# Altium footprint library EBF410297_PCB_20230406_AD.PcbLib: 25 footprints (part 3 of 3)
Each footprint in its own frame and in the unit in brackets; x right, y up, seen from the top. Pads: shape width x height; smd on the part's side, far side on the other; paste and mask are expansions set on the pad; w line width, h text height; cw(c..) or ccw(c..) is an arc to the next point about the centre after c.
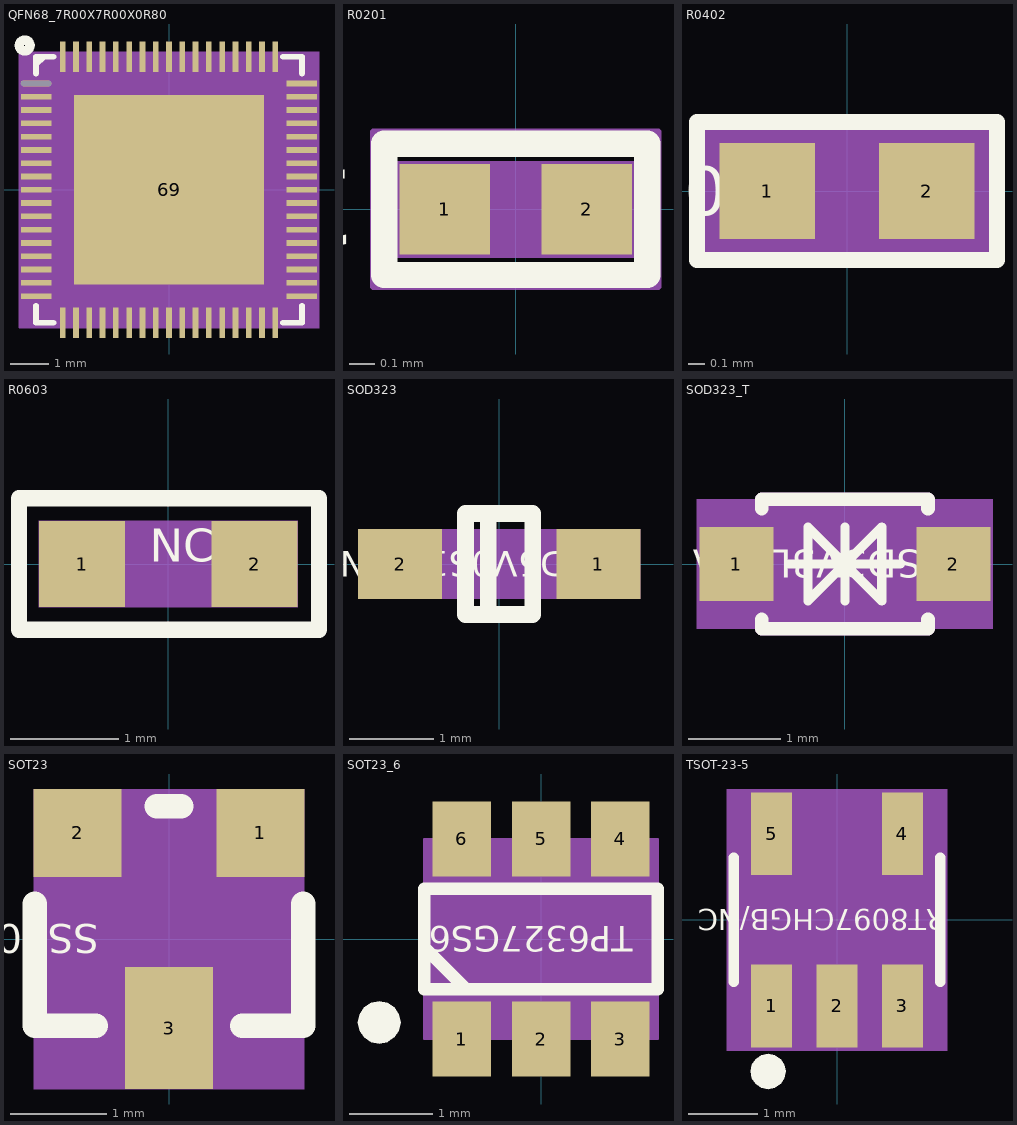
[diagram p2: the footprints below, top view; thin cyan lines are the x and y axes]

## QFN68_7R00X7R00X0R80 [mil] "QFN68_7R00X7R00X0R80"
pads (69):
  oval 31.5x5.9 smd: 1(-137.8,110.24)
  rect 31.5x5.9 smd: 2(-137.8,96.46) 3(-137.8,82.68) 4(-137.8,68.9) 5(-137.8,55.12) 6(-137.8,41.34) 7(-137.8,27.56) 8(-137.8,13.78) 9(-137.8,0) 10(-137.8,-13.78) 11(-137.8,-27.56) 12(-137.8,-41.34) 13(-137.8,-55.12) 14(-137.8,-68.9) 15(-137.8,-82.68) 16(-137.8,-96.46) 17(-137.8,-110.24) 35(137.8,-110.24) 36(137.8,-96.46) 37(137.8,-82.68) 38(137.8,-68.9) 39(137.8,-55.12) 40(137.8,-41.34) 41(137.8,-27.56) 42(137.8,-13.78) 43(137.8,0) 44(137.8,13.78) 45(137.8,27.56) 46(137.8,41.34) 47(137.8,55.12) 48(137.8,68.9) 49(137.8,82.68) 50(137.8,96.46) 51(137.8,110.24)
  rect 5.9x31.5 smd: 18(-110.24,-137.8) 19(-96.46,-137.8) 20(-82.68,-137.8) 21(-68.9,-137.8) 22(-55.12,-137.8) 23(-41.34,-137.8) 24(-27.56,-137.8) 25(-13.78,-137.8) 26(0,-137.8) 27(13.78,-137.8) 28(27.56,-137.8) 29(41.34,-137.8) 30(55.12,-137.8) 31(68.9,-137.8) 32(82.68,-137.8) 33(96.46,-137.8) 34(110.24,-137.8) 52(110.24,137.8) 53(96.46,137.8) 54(82.68,137.8) 55(68.9,137.8) 56(55.12,137.8) 57(41.34,137.8) 58(27.56,137.8) 59(13.78,137.8) 60(0,137.8) 61(-13.78,137.8) 62(-27.56,137.8) 63(-41.34,137.8) 64(-55.12,137.8) 65(-68.9,137.8) 66(-82.68,137.8) 67(-96.46,137.8) 68(-110.24,137.8)
  rect 196.85x196.85 smd: 69(0,0)
Top Overlay:
  circle w9.84: c-149.61,149.61 r5.56
  lines w5.91: -137.8,-120.08 -137.8,-137.8 -119.69,-137.8 ; -137.8,120.47 -137.8,137.8 -119.69,137.8 ; -137.8,129.92 -129.92,137.8 ; 118.11,-137.8 137.8,-137.8 137.8,-120.08 ; 118.11,137.8 137.8,137.8 137.8,120.47
  text "RK809-5" at 0,-27.6 h12
Top 3D Body:
  region: -155.51,-142.91 155.51,-142.91 155.51,142.91 -155.51,142.91
Mechanical 14:
  text "51" at 137.8,90.24 h25
  text "7" at -137.8,17.56 h25
  text "65" at -68.9,117.8 h25
  text "50" at 137.8,76.46 h25
  text "25" at -13.78,-157.8 h25
  text "1" at -137.8,100.24 h25
  text "2" at -137.8,86.46 h25
  text "34" at 110.24,-157.8 h25
  text "32" at 82.68,-157.8 h25
  text "27" at 13.78,-157.8 h25
  text "52" at 110.24,117.8 h25
  text "33" at 96.46,-157.8 h25
  text "36" at 137.8,-116.46 h25
  text "37" at 137.8,-102.68 h25
  text "38" at 137.8,-88.9 h25
  text "35" at 137.8,-130.24 h25
  text "48" at 137.8,48.9 h25
  text "44" at 137.8,-6.22 h25
  text "53" at 96.46,117.8 h25
  text "16" at -137.8,-116.46 h25
  text "15" at -137.8,-102.68 h25
  text "14" at -137.8,-88.9 h25
  text "17" at -137.8,-130.24 h25
  text "18" at -110.24,-157.8 h25
  text "19" at -96.46,-157.8 h25
  text "43" at 137.8,-20 h25
  text "42" at 137.8,-33.78 h25
  text "59" at 13.78,117.8 h25
  text "55" at 68.9,117.8 h25
  text "67" at -96.46,117.8 h25
  text "47" at 137.8,35.12 h25
  text "63" at -41.34,117.8 h25
  text "62" at -27.56,117.8 h25
  text "69" at 0,-20 h25
  text "56" at 55.12,117.8 h25
  text "3" at -137.8,72.68 h25
  text "8" at -137.8,3.78 h25
  text "64" at -55.12,117.8 h25
  text "58" at 27.56,117.8 h25
  text "6" at -137.8,31.34 h25
  text "5" at -137.8,45.12 h25
  text "31" at 68.9,-157.8 h25
  text "12" at -137.8,-61.34 h25
  text "29" at 41.34,-157.8 h25
  text "28" at 27.56,-157.8 h25
  text "20" at -82.68,-157.8 h25
  text "21" at -68.9,-157.8 h25
  text "23" at -41.34,-157.8 h25
  text "54" at 82.68,117.8 h25
  text "57" at 41.34,117.8 h25
  text "66" at -82.68,117.8 h25
  text "11" at -137.8,-47.56 h25
  text "10" at -137.8,-33.78 h25
  text "22" at -55.12,-157.8 h25
  text "30" at 55.12,-157.8 h25
  text "24" at -27.56,-157.8 h25
  text "4" at -137.8,58.9 h25
  text "46" at 137.8,21.34 h25
  text "39" at 137.8,-75.12 h25
  text "41" at 137.8,-47.56 h25
  text "40" at 137.8,-61.34 h25
  text "61" at -13.78,117.8 h25
  text "49" at 137.8,62.68 h25
  text "26" at 0,-157.8 h25
  text "68" at -110.24,117.8 h25
  text "13" at -137.8,-75.12 h25
  text "9" at -137.8,-10 h25
  text "45" at 137.8,7.56 h25
  text "60" at 0,117.8 h25
Top Assembly:
  lines w1: -155.51,-142.91 -155.51,142.91 155.51,142.91 155.51,-142.91 -155.51,-142.91
  text ".Designator" at 0,0 h60
3D body: height 150, standoff 0, extent -155.51,-142.91 155.51,142.91

## R0201 [mm] "R0201"
pads (2):
  rect 0.35x0.35 smd: 1(-0.275,0) 2(0.275,0)
Top Overlay:
  lines w0.102: -0.508,-0.254 0.508,-0.254 0.508,0.254 -0.508,0.254 -0.508,-0.254
  text "1.62K" at -0.61,0.152 h0.3
Top 3D Body:
  region: -0.475,-0.175 -0.475,0.175 0.475,0.175 0.475,-0.175
Mechanical 14:
  text "1" at -0.59,0 h0.79
  text "2" at -0.04,0 h0.79
Top Assembly:
  lines w0.025: -0.55,-0.3 -0.55,0.3 0.55,0.3 0.55,-0.3 -0.55,-0.3 ; -0.475,-0.175 -0.475,0.175 0.475,0.175 0.475,-0.175 -0.475,-0.175
  text ".Designator" at 0,0 h0.79
  text "1.62K" at 0,0 h0.79
3D body: height 3.81, standoff 0, extent -0.475,-0.175 0.475,0.175

## R0402 [mm] "R0402"
pads (2):
  rect 0.599x0.599 smd: 1(-0.5,0) 2(0.5,0)
Top Overlay:
  lines w0.102: -0.94,-0.432 -0.94,0.432 0.94,0.432 0.94,-0.432 -0.94,-0.432
  text "200R" at -0.488,0.152 h0.3
Top 3D Body:
  region: 0.94,0.432 0.94,-0.432 -0.94,-0.432 -0.94,0.432
Mechanical 14:
  text "2" at 0.246,0 h0.64
  text "1" at -0.754,0 h0.64
Top Assembly:
  dashed: -0.94,-0.432 -0.94,0.432 0.94,0.432 0.94,-0.432
3D body: height 3.81, standoff 0, extent -0.94,-0.432 0.94,0.432

## R0603 [mm] "R0603"
pads (2):
  rect 0.8x0.8 smd: 1(-0.8,0) 2(0.8,0)
Top Overlay:
  lines w0.152: -1.384,-0.61 -1.384,0.61 1.397,0.61 1.397,-0.61 -1.384,-0.61
  text "NC" at -0.172,0.02 h0.3
Top 3D Body:
  region: -1.2,-0.4 1.2,-0.4 1.2,0.4 -1.2,0.4
Mechanical 14:
  text "2" at 0.477,0.323 h1.14
  text "1" at -1.123,0.323 h1.14
3D body: height 3.81, standoff 0, extent -1.2,-0.4 1.2,0.4

## SOD323 [mm] "SOD323"
pads (2):
  rect 1x0.83 smd: 1(1.18,0) 2(-1.18,0)
Top Overlay:
  lines w0.2: -0.13,-0.6 -0.13,0.6 ; -0.4,-0.6 0.4,-0.6 0.4,0.6 -0.4,0.6 -0.4,-0.6
  text "PESD5V0S1BA-N" at 1.585,0.152 h0.3
Top 3D Body:
  region: -1.68,-0.415 1.68,-0.415 1.68,0.415 -1.68,0.415
Mechanical 14:
  text "1" at 1.302,0 h0.3
  text "2" at -1.058,0 h0.3
3D body: height 3.81, standoff 0, extent -1.68,-0.415 1.68,0.415

## SOD323_T [mil] "SOD323_T"
pads (2):
  rect 31.5x31.5 smd: 1(-46.26,0) 2(46.26,0)
Top Overlay:
  lines w3.94: -23.62,0 23.62,0 ; 0,-15.75 0,15.75 ; 0,0 -15.75,-15.75 -15.75,15.75 0,0 ; 0,0 15.75,15.75 15.75,-15.75 0,0
  lines w5.91: -35.43,-23.62 -35.43,-27.56 35.43,-27.56 35.43,-23.62 ; -35.43,23.62 -35.43,27.56 35.43,27.56 35.43,23.62
  text "PESD3V3L1BA" at 52.8,6 h12
Top 3D Body:
  region: -62.99,27.56 -62.99,-27.56 62.99,-27.56 62.99,27.56
Mechanical 14:
  text "2" at 56.26,0 h25
  text "1" at -36.26,0 h25
Top Assembly:
  lines w5.91: -35.43,-27.56 35.43,-27.56 35.43,27.56 -35.43,27.56 -35.43,-27.56
3D body: height 150, standoff 0, extent -62.99,-27.56 62.99,27.56

## SOT23 [mil] "SOT23"
pads (3):
  rect 36x36 smd: 1(37.5,43.5) 2(-37.5,43.5)
  rect 36x50 smd: 3(0,-36.5)
Top Overlay:
  lines w10: -55,14.5 -55,-35.5 -30,-35.5 ; -5,54.5 5,54.5 ; 30,-35.5 55,-35.5 55,14.5
  text "SS8050" at -28.8,6 h12
Top 3D Body:
  region: 55.5,61.5 55.5,-61.5 -55.5,-61.5 -55.5,61.5
Mechanical 14:
  text "2" at -55.5,43.5 h45
  text "1" at 19.5,43.5 h45
  text "3" at -18,-36.5 h45
3D body: height 150, standoff 0, extent -55.5,-61.5 55.5,61.5

## SOT23_6 [mm] "SOT23_6"
pads (6):
  rect 0.7x0.9 smd: 1(-0.95,-1.2) 2(0,-1.2) 3(0.95,-1.2) 4(0.95,1.2) 5(0,1.2) 6(-0.95,1.2)
Top Overlay:
  dashed: -2.195,-1 -2.175,-1.098 -2.12,-1.18 -2.038,-1.235 -1.94,-1.255 -1.843,-1.235 -1.815,-1.217 -1.76,-1.18 -1.705,-1.098 -1.685,-1 -1.705,-0.902 -1.76,-0.82 -1.815,-0.783 -1.843,-0.765 -1.94,-0.745 -2.038,-0.765 -2.12,-0.82 -2.175,-0.902
  lines w0.15: -1.4,-0.1 -0.9,-0.6 ; -1.4,-0.6 1.4,-0.6 1.4,0.6 -1.4,0.6 -1.4,-0.6
  text "TP6327GS6" at 1.097,0.152 h0.3
Top 3D Body:
  region: -1.4,-1.2 1.4,-1.2 1.4,1.2 -1.4,1.2
Mechanical 14:
  text "3" at 1.204,-1.2 h0.64
  text "1" at -0.696,-1.2 h0.64
  text "4" at 1.204,1.2 h0.64
  text "5" at 0.254,1.2 h0.64
  text "2" at 0.254,-1.2 h0.64
  text "6" at -0.696,1.2 h0.64
Top Assembly:
  lines w0.025: -1.4,-1.2 -1.4,1.2 1.4,1.2 1.4,-1.2 -1.4,-1.2
3D body: height 3.81, standoff 0, extent -1.4,-1.2 1.4,1.2

## TSOT-23-5 [mm] "TSOT-23-5"
pads (5):
  rect 0.599x1.199 smd: 1(-0.95,-1.25) 2(0,-1.25) 3(0.95,-1.25) 4(0.95,1.25) 5(-0.95,1.25)
Top Overlay:
  dashed: -1.255,-2.2 -1.235,-2.297 -1.18,-2.38 -1.098,-2.435 -1,-2.455 -0.902,-2.435 -0.875,-2.417 -0.82,-2.38 -0.765,-2.297 -0.745,-2.2 -0.765,-2.102 -0.82,-2.02 -0.875,-1.983 -0.902,-1.964 -1,-1.945 -1.098,-1.964 -1.18,-2.02 -1.235,-2.102
  lines w0.15: -1.5,-0.9 -1.5,0.9 ; 1.5,-0.9 1.5,0.9
  text "RT8097CHGB/NC" at 1.585,0.152 h0.3
Top 3D Body:
  region: -1.6,1.9 -1.6,-1.9 1.6,-1.9 1.6,1.9
Mechanical 14:
  text "2" at 0.051,-1.25 h0.13
  text "4" at 1.001,1.25 h0.13
  text "1" at -0.899,-1.25 h0.13
  text "5" at -0.899,1.25 h0.13
  text "3" at 1.001,-1.25 h0.13
Top Assembly:
  lines w0.15: -1.5,-0.85 -1.5,0.85 1.5,0.85 1.5,-0.85 -1.5,-0.85
3D body: height 3.81, standoff 0, extent -1.6,-1.9 1.6,1.9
